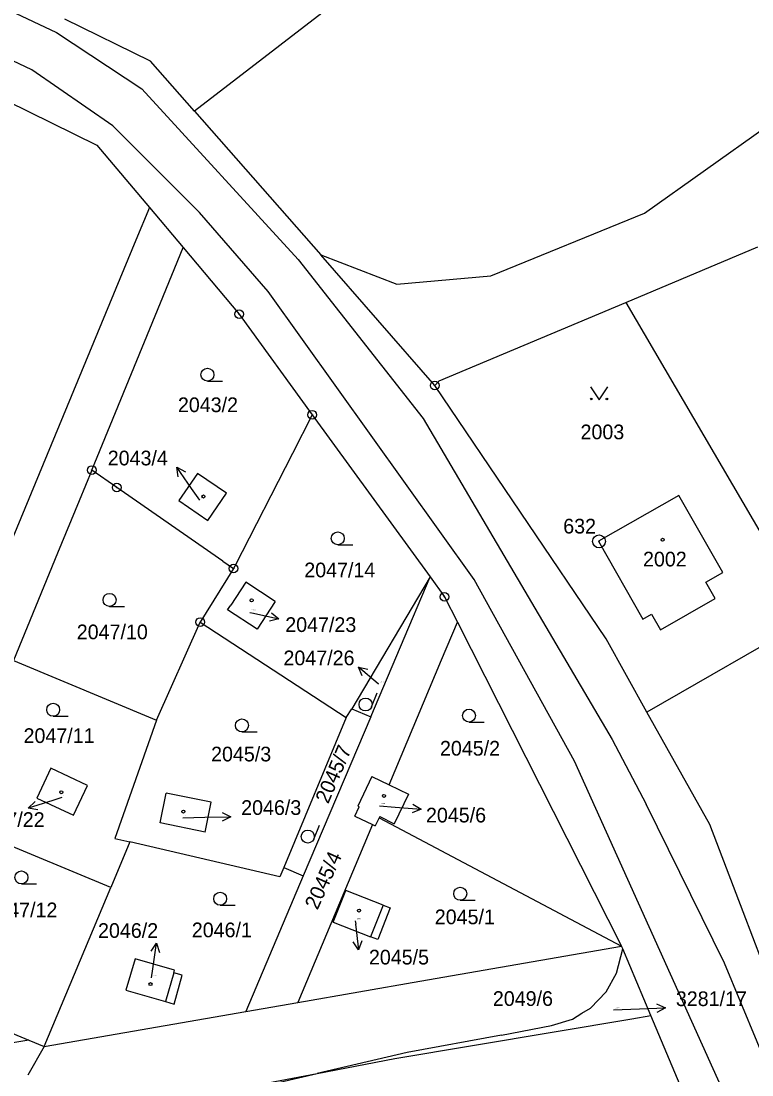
# Model space of a CAD drawing. Extents: x -736345 to -729997, y -1130177 to -1122501.
# Drawn here: x -732679.3 to -732594.8, y -1127886.3 to -1127764.4 of the extents above; entities that cross this region are included whole.
import ezdxf

# ---------------------------------------------------------------- set-up
doc = ezdxf.new("R2010")
doc.units = 0
for name, color, linetype in [('Vrstva 1', 7, 'Continuous'), ('Vrstva 16', 7, 'Continuous'), ('Vrstva 17', 7, 'Continuous'), ('Vrstva 18', 7, 'Continuous'), ('Vrstva 19', 7, 'Continuous'), ('Vrstva 25', 7, 'Continuous'), ('Vrstva 4', 7, 'Continuous')]:
    doc.layers.add(name, color=color, linetype=linetype)

msp = doc.modelspace()

# ---------------------------------------------------------------- linework, layer by layer
at = {"layer": 'Vrstva 1'}
for points in [[(-732639.53, -1127759.63), (-732659.27, -1127774.86)], [(-732699.33, -1127764.64), (-732670.55, -1127778.8)], [(-732664.36, -1127769.06), (-732674.26, -1127764.21)], [(-732659.27, -1127774.86), (-732664.36, -1127769.06)], [(-732659.27, -1127774.86), (-732644.65, -1127791.46)], [(-732607.19, -1127786.66), (-732593.1, -1127776.63)], [(-732670.55, -1127778.8), (-732664.48, -1127786.01)], [(-732664.48, -1127786.01), (-732666.05, -1127789.79)], [(-732664.48, -1127786.01), (-732660.58, -1127790.63)], [(-732625, -1127793.9), (-732607.19, -1127786.66)], [(-732666.05, -1127789.79), (-732680.75, -1127825.28)], [(-732663.21, -1127797.03), (-732660.58, -1127790.63)], [(-732660.58, -1127790.63), (-732654.11, -1127798.32)], [(-732609.37, -1127796.98), (-732594.08, -1127790.55)], [(-732644.65, -1127791.46), (-732635.86, -1127794.87)], [(-732631.48, -1127806.58), (-732644.65, -1127791.46)], [(-732635.86, -1127794.87), (-732625, -1127793.9)], [(-732671.16, -1127816.36), (-732663.21, -1127797.03)], [(-732630.96, -1127806.06), (-732609.37, -1127796.98)], [(-732609.37, -1127796.98), (-732588.01, -1127833.49)], [(-732654.11, -1127798.32), (-732645.65, -1127809.96)], [(-732631.48, -1127806.58), (-732630.96, -1127806.06)], [(-732611.66, -1127835.87), (-732631.48, -1127806.58)], [(-732645.65, -1127809.96), (-732647.94, -1127814.44)], [(-732645.65, -1127809.96), (-732632.01, -1127828.73)], [(-732647.94, -1127814.44), (-732654.61, -1127827.48)], [(-732671.16, -1127816.36), (-732672.63, -1127819.93)], [(-732668.27, -1127818.37), (-732671.16, -1127816.36)], [(-732658.92, -1127816.74), (-732661.09, -1127819.88)], [(-732655.58, -1127819.05), (-732658.92, -1127816.74)], [(-732656.01, -1127826.89), (-732668.27, -1127818.37)], [(-732672.63, -1127819.93), (-732675.11, -1127825.96)], [(-732661.09, -1127819.88), (-732657.74, -1127822.19)], [(-732657.74, -1127822.19), (-732655.58, -1127819.05)], [(-732603.25, -1127819.29), (-732612.52, -1127824.58)], [(-732598.16, -1127828.21), (-732603.25, -1127819.29)], [(-732612.52, -1127824.58), (-732607.4, -1127833.6)], [(-732675.11, -1127825.96), (-732680.21, -1127838.37)], [(-732656.01, -1127826.89), (-732654.76, -1127827.76)], [(-732654.76, -1127827.76), (-732658.6, -1127833.94)], [(-732654.61, -1127827.48), (-732654.76, -1127827.76)], [(-732600.11, -1127829.33), (-732598.16, -1127828.21)], [(-732653.33, -1127829.33), (-732655.07, -1127831.97)], [(-732649.92, -1127831.58), (-732653.33, -1127829.33)], [(-732632.01, -1127828.73), (-732641.07, -1127843.98)], [(-732638.88, -1127844.9), (-732632.01, -1127828.73)], [(-732632.01, -1127828.73), (-732630.35, -1127831.02)], [(-732599.04, -1127831.2), (-732600.11, -1127829.33)], [(-732630.35, -1127831.02), (-732628.86, -1127833.95)], [(-732655.44, -1127832.53), (-732655.07, -1127831.97)], [(-732649.92, -1127831.58), (-732652.03, -1127834.78)], [(-732605.36, -1127834.83), (-732599.04, -1127831.2)], [(-732652.03, -1127834.78), (-732655.44, -1127832.53)], [(-732607.4, -1127833.6), (-732606.39, -1127833.02)], [(-732588.01, -1127833.49), (-732606.92, -1127844.35)], [(-732606.39, -1127833.02), (-732605.36, -1127834.83)], [(-732663.65, -1127845.28), (-732658.6, -1127833.94)], [(-732658.6, -1127833.94), (-732641.72, -1127844.97)], [(-732630.69, -1127838.32), (-732628.86, -1127833.95)], [(-732628.86, -1127833.95), (-732609.85, -1127871.44)], [(-732606.92, -1127844.35), (-732611.66, -1127835.87)], [(-732680.21, -1127838.37), (-732663.65, -1127845.28)], [(-732636.76, -1127852.77), (-732630.69, -1127838.32)], [(-732641.72, -1127844.97), (-732641.07, -1127843.98)], [(-732641.07, -1127843.98), (-732638.88, -1127844.9)], [(-732599.63, -1127857.37), (-732606.92, -1127844.35)], [(-732663.65, -1127845.28), (-732668.5, -1127858.96)], [(-732641.72, -1127844.97), (-732648.94, -1127862.35)], [(-732638.88, -1127844.9), (-732646.68, -1127863.31)], [(-732675.89, -1127850.86), (-732677.5, -1127854.32)], [(-732671.64, -1127852.83), (-732675.89, -1127850.86)], [(-732673.25, -1127856.29), (-732671.64, -1127852.83)], [(-732638.75, -1127851.82), (-732640.38, -1127855.22)], [(-732638.75, -1127851.82), (-732636.76, -1127852.77)], [(-732636.76, -1127852.77), (-732634.53, -1127853.84)], [(-732663.26, -1127857.17), (-732662.56, -1127853.72)], [(-732657.34, -1127854.79), (-732662.56, -1127853.72)], [(-732634.53, -1127853.84), (-732636.18, -1127857.28)], [(-732677.5, -1127854.32), (-732673.25, -1127856.29)], [(-732658.04, -1127858.23), (-732657.34, -1127854.79)], [(-732640.71, -1127856.38), (-732640.2, -1127855.31)], [(-732640.38, -1127855.22), (-732640.2, -1127855.31)], [(-732640.71, -1127856.38), (-732638.69, -1127857.35)], [(-732637.9, -1127856.58), (-732638.35, -1127857.51)], [(-732637.83, -1127856.45), (-732637.9, -1127856.58)], [(-732637.9, -1127856.58), (-732609.85, -1127871.44)], [(-732637.83, -1127856.45), (-732636.18, -1127857.28)], [(-732668.96, -1127864.66), (-732687.8, -1127856.81)], [(-732658.04, -1127858.23), (-732663.26, -1127857.17)], [(-732638.69, -1127857.35), (-732647.33, -1127877.95)], [(-732638.69, -1127857.35), (-732638.35, -1127857.51)], [(-732595.79, -1127867.46), (-732599.63, -1127857.37)], [(-732668.5, -1127858.96), (-732666.74, -1127859.37)], [(-732666.74, -1127859.37), (-732668.96, -1127864.66)], [(-732649.39, -1127863.42), (-732666.74, -1127859.37)], [(-732648.94, -1127862.35), (-732649.39, -1127863.42)], [(-732648.94, -1127862.35), (-732646.68, -1127863.31)], [(-732646.68, -1127863.31), (-732653.33, -1127878.99)], [(-732676.65, -1127883.04), (-732668.96, -1127864.66)], [(-732643.21, -1127868.66), (-732641.77, -1127865)], [(-732637.45, -1127866.69), (-732641.77, -1127865)], [(-732636.62, -1127867.01), (-732638.05, -1127870.67)], [(-732637.45, -1127866.69), (-732636.62, -1127867.01)], [(-732581.25, -1127905.55), (-732595.79, -1127867.46)], [(-732643.21, -1127868.66), (-732638.91, -1127870.34)], [(-732638.05, -1127870.67), (-732638.91, -1127870.34)], [(-732633.2, -1127875.49), (-732609.85, -1127871.44)], [(-732610.43, -1127874.57), (-732609.72, -1127871.73)], [(-732609.72, -1127871.73), (-732609.85, -1127871.44)], [(-732606.47, -1127879.46), (-732609.72, -1127871.73)], [(-732666.15, -1127872.9), (-732667.2, -1127876.52)], [(-732661.57, -1127874.22), (-732666.15, -1127872.9)], [(-732661.65, -1127874.52), (-732661.57, -1127874.22)], [(-732660.69, -1127874.79), (-732661.65, -1127874.52)], [(-732661.64, -1127878.12), (-732660.69, -1127874.79)], [(-732611.64, -1127876.7), (-732610.43, -1127874.57)], [(-732695.38, -1127875.24), (-732678.45, -1127882.29)], [(-732647.33, -1127877.95), (-732633.2, -1127875.49)], [(-732667.2, -1127876.52), (-732662.61, -1127877.84)], [(-732613.46, -1127878.59), (-732611.64, -1127876.7)], [(-732662.61, -1127877.84), (-732661.64, -1127878.12)], [(-732653.33, -1127878.99), (-732647.33, -1127877.95)], [(-732614.45, -1127879.19), (-732613.46, -1127878.59)], [(-732676.65, -1127883.04), (-732653.33, -1127878.99)], [(-732636.08, -1127884.44), (-732608.66, -1127879.83)], [(-732615.55, -1127879.87), (-732614.45, -1127879.19)], [(-732608.66, -1127879.83), (-732606.47, -1127879.46)], [(-732602.15, -1127889.7), (-732606.47, -1127879.46)], [(-732623.77, -1127881.71), (-732617.96, -1127880.62)], [(-732617.96, -1127880.62), (-732615.55, -1127879.87)], [(-732623.77, -1127881.71), (-732634.65, -1127883.73)], [(-732678.45, -1127882.29), (-732699.73, -1127885.83)], [(-732676.65, -1127883.04), (-732678.57, -1127886.36)], [(-732678.45, -1127882.29), (-732676.65, -1127883.04)], [(-732634.65, -1127883.73), (-732645.08, -1127886.15)], [(-732645.08, -1127886.15), (-732636.08, -1127884.44)], [(-732675.82, -1127893.28), (-732645.08, -1127886.15)], [(-732664.24, -1127889.79), (-732645.08, -1127886.15)]]:
    msp.add_lwpolyline(points, dxfattribs=at)
at = {"layer": 'Vrstva 16'}
for points in [[(-732658.65, -1127819.85), (-732659.6, -1127818.49)], [(-732652.88, -1127832.82), (-732652.43, -1127832.92)], [(-732637.94, -1127841.12), (-732638.01, -1127841.07)], [(-732674.63, -1127854.24), (-732675.65, -1127854.57)], [(-732637.85, -1127855.19), (-732636.04, -1127855.34)], [(-732660.62, -1127856.57), (-732658.07, -1127856.52)], [(-732640.67, -1127868.51), (-732640.62, -1127868.87)], [(-732664.25, -1127875.08), (-732664.1, -1127874.06)], [(-732610.8, -1127878.8), (-732607.78, -1127878.68)]]:
    msp.add_lwpolyline(points, dxfattribs=at)
at = {"layer": 'Vrstva 25'}
for points in [[(-732657.77, -1127806.08), (-732656.02, -1127806.08)], [(-732613.46, -1127806.74), (-732612.46, -1127808.24), (-732611.46, -1127806.74)], [(-732659.6, -1127818.49), (-732661.307, -1127816.024)], [(-732661.149, -1127817.131), (-732661.307, -1127816.024), (-732660.327, -1127816.562)], [(-732642.69, -1127825.01), (-732640.94, -1127825.01)], [(-732669.1, -1127832.13), (-732667.35, -1127832.13)], [(-732652.43, -1127832.92), (-732649.503, -1127833.574)], [(-732650.37, -1127832.869), (-732649.503, -1127833.574), (-732650.588, -1127833.844)], [(-732638.01, -1127841.07), (-732640.308, -1127839.142)], [(-732639.863, -1127840.168), (-732640.308, -1127839.142), (-732639.22, -1127839.402)], [(-732638.78, -1127843.75), (-732638.142, -1127842.121)], [(-732675.62, -1127844.84), (-732673.87, -1127844.84)], [(-732627.51, -1127845.51), (-732625.76, -1127845.51)], [(-732653.78, -1127846.65), (-732652.03, -1127846.65)], [(-732675.65, -1127854.57), (-732678.506, -1127855.487)], [(-732677.401, -1127855.657), (-732678.506, -1127855.487), (-732677.707, -1127854.705)], [(-732636.05, -1127855.34), (-732633.061, -1127855.591)], [(-732634.016, -1127855.01), (-732633.061, -1127855.591), (-732634.099, -1127856.005)], [(-732658.07, -1127856.52), (-732655.071, -1127856.458)], [(-732656.081, -1127855.979), (-732655.071, -1127856.458), (-732656.06, -1127856.978)], [(-732645.47, -1127859.04), (-732644.801, -1127857.424)], [(-732679.3, -1127864.23), (-732677.55, -1127864.23)], [(-732628.53, -1127866.12), (-732626.78, -1127866.12)], [(-732656.3, -1127866.69), (-732654.55, -1127866.69)], [(-732640.63, -1127868.87), (-732640.296, -1127871.851)], [(-732664.298, -1127872.009), (-732663.657, -1127871.093), (-732663.31, -1127872.156)], [(-732664.1, -1127874.06), (-732663.657, -1127871.093)], [(-732639.911, -1127870.801), (-732640.296, -1127871.851), (-732640.903, -1127870.913)], [(-732607.78, -1127878.68), (-732604.783, -1127878.565)], [(-732605.801, -1127878.104), (-732604.783, -1127878.565), (-732605.763, -1127879.102)]]:
    msp.add_lwpolyline(points, dxfattribs=at)
for centre, radius in [((-732654.11, -1127798.32), 0.5), ((-732654.11, -1127798.32), 0.032), ((-732657.77, -1127805.33), 0.75), ((-732631.48, -1127806.58), 0.5), ((-732631.48, -1127806.58), 0.032), ((-732613.36, -1127808.14), 0.1), ((-732611.56, -1127808.14), 0.1), ((-732645.65, -1127809.96), 0.5), ((-732645.65, -1127809.96), 0.032), ((-732671.16, -1127816.36), 0.5), ((-732671.16, -1127816.36), 0.032), ((-732668.27, -1127818.37), 0.5), ((-732668.27, -1127818.37), 0.032), ((-732658.23, -1127819.42), 0.175), ((-732642.69, -1127824.26), 0.75), ((-732612.47, -1127824.61), 0.75), ((-732612.47, -1127824.61), 0.032), ((-732605.11, -1127824.43), 0.175), ((-732654.76, -1127827.76), 0.5), ((-732654.76, -1127827.76), 0.032), ((-732669.1, -1127831.38), 0.75), ((-732630.35, -1127831.02), 0.5), ((-732630.35, -1127831.02), 0.032), ((-732652.66, -1127831.43), 0.175), ((-732658.6, -1127833.94), 0.5), ((-732658.6, -1127833.94), 0.032), ((-732639.478, -1127843.477), 0.749), ((-732675.62, -1127844.09), 0.75), ((-732627.51, -1127844.76), 0.75), ((-732653.78, -1127845.9), 0.75), ((-732674.68, -1127853.62), 0.175), ((-732637.35, -1127854.05), 0.175), ((-732660.56, -1127855.86), 0.175), ((-732646.162, -1127858.753), 0.749), ((-732679.3, -1127863.48), 0.75), ((-732656.3, -1127865.94), 0.75), ((-732628.53, -1127865.37), 0.75), ((-732640.23, -1127867.31), 0.175), ((-732664.36, -1127875.82), 0.175)]:
    msp.add_circle(centre, radius, dxfattribs=at)
at = {"layer": 'Vrstva 4'}
for points in [[(-732704.4, -1127751.97), (-732675.23, -1127765.75)], [(-732678.08, -1127770.08), (-732706.61, -1127756.55)], [(-732675.23, -1127765.75), (-732665.35, -1127772.25)], [(-732668.71, -1127776.56), (-732678.08, -1127770.08)], [(-732665.35, -1127772.25), (-732647.29, -1127792)], [(-732658.68, -1127786.57), (-732668.71, -1127776.56)], [(-732650.75, -1127795.72), (-732658.68, -1127786.57)], [(-732647.29, -1127792), (-732632.81, -1127810.38)], [(-732626.92, -1127829.01), (-732650.75, -1127795.72)], [(-732632.81, -1127810.38), (-732610.94, -1127847.54)], [(-732615.32, -1127850.02), (-732626.92, -1127829.01)], [(-732610.94, -1127847.54), (-732607, -1127855.02)], [(-732589.39, -1127907.51), (-732615.32, -1127850.02)], [(-732597.95, -1127873.39), (-732607, -1127855.02)], [(-732637.45, -1127866.69), (-732638.91, -1127870.34)], [(-732584.72, -1127905.23), (-732597.95, -1127873.39)], [(-732661.65, -1127874.52), (-732662.61, -1127877.84)]]:
    msp.add_lwpolyline(points, dxfattribs=at)

# ---------------------------------------------------------------- texts
at = {"layer": 'Vrstva 16'}
for s, p in [('2043/4', (-732669.307, -1127815.82)), ('2047/23', (-732648.77, -1127835.09)), ('2047/26', (-732648.977, -1127838.94)), ('2046/3', (-732653.87, -1127856.25)), ('2045/6', (-732632.49, -1127857.12)), ('2047/22', (-732684.827, -1127857.64)), ('2046/2', (-732670.43, -1127870.47)), ('2045/5', (-732639.09, -1127873.55)), ('3281/17', (-732603.58, -1127878.36))]:
    msp.add_text(s, height=1.7, dxfattribs=at).set_placement(p)
at = {"layer": 'Vrstva 17'}
msp.add_text('632', height=1.7, dxfattribs=at).set_placement((-732616.61, -1127823.7))
at = {"layer": 'Vrstva 18'}
for s, height, p in [('2043/2', 1.7, (-732661.19, -1127809.66)), ('2003', 1.7, (-732614.61, -1127812.8)), ('2047/14', 1.7, (-732646.57, -1127828.77)), ('2047/10', 1.7, (-732672.89, -1127835.93)), ('2047/26', 0.1, (-732637.74, -1127840.93)), ('2047/11', 1.7, (-732679.05, -1127847.93)), ('2045/2', 1.7, (-732630.87, -1127849.39)), ('2045/3', 1.7, (-732657.35, -1127850.06)), ('2047/12', 1.7, (-732683.35, -1127868.09)), ('2045/1', 1.7, (-732631.47, -1127868.89)), ('2046/1', 1.7, (-732659.58, -1127870.4)), ('2049/6', 1.7, (-732624.75, -1127878.34)), ('3281/17', 0.1, (-732610.6, -1127878.6))]:
    msp.add_text(s, height=height, dxfattribs=at).set_placement(p)
for s, rotation, p in [('2045/7', 66.70053, (-732643.804, -1127855.048)), ('2045/4', 65.70052, (-732645.039, -1127867.316))]:
    msp.add_text(s, height=1.7, rotation=rotation, dxfattribs=at).set_placement(p)
at = {"layer": 'Vrstva 19'}
for s, height, p in [('2043/4', 0.1, (-732658.45, -1127819.65)), ('2002', 1.7, (-732607.38, -1127827.51)), ('2047/23', 0.1, (-732652.68, -1127832.62)), ('2047/22', 0.1, (-732674.43, -1127854.04)), ('2045/6', 0.1, (-732637.65, -1127854.99)), ('2046/3', 0.1, (-732660.43, -1127856.35)), ('2045/5', 0.1, (-732640.47, -1127868.31)), ('2046/2', 0.1, (-732664.05, -1127874.88))]:
    msp.add_text(s, height=height, dxfattribs=at).set_placement(p)

doc.saveas('drawing.dxf')
